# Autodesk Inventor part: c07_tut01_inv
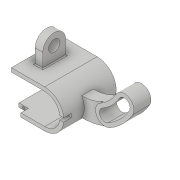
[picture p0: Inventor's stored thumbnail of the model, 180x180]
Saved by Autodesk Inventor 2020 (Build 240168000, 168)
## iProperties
Created: 2017-04
Part Number: c07_tut01_inv
Material: Generic
Document SubType Name: Modeling
Designer: CADCIM 00
Density: 1 g/cm^3
Appearance: Default
Author: CADCIM 00
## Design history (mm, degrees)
sketch "Sketch1"
  geometry: L1 (0, 16)-(35, 16); L2 (35, 16)-(35, 20); L3 (35, 20)-(0, 20); L4 (0, -20)-(35, -20); L5 (35, -20)-(35, -16); L6 (35, -16)-(0, -16); A1 r 16 centre (0, 0) between (0, 16) and (0, -16); A2 r 20 centre (0, 0) between (0, 20) and (0, -20); 1 further point
  constraints: 12 end point, 4 point on circle, 4 tangent, 3 perpendicular, 2 centre point, 2 point on line, 1 coincident, 1 concentric, 1 horizontal, 1 parallel
  dimensions: "d1" = 20 radius of A2; "d3" = 35 distance from line of point (0, 0) L5; "d37" = 16 radius of A1
extrude "Extrusion1" new body sketch "Sketch1" stored distance "d4" = 55; taper "d5" = 0 deg
sketch "Sketch2"
  geometry: A1 r 45 centre (-17.5, 55) between (-56.409, 32.393) and (-17.32, 10); A2 r 65 centre (-17.5, 55) between (-73.702, 22.345) and (-17.321, -10); A3 r 10 centre (-65.055, 27.369) between (-56.409, 32.393) and (-73.702, 22.345); A4 r 20 centre (0, 0) between (0, 20) and (0, -20) reference; A5 r 20 centre (0, 0) between (-17.32, 10) and (-17.321, -10); 1 further point
  constraints: 10 point on circle, 4 centre point, 2 tangent, 1 coincident
  dimensions: "d6" = 45 radius of A1; "d7" = 65 radius of A2; "d8" = 17.5 horizontal distance of point (0, 0) A1.centre; "d9" = 55 vertical distance of point (0, 0) A1.centre; "d10" = 60 deg dimension on A1.centre A3.centre A2.end
extrude "Extrusion2" join sketch "Sketch2" stored distance "d11" = 12; taper "d12" = 0 deg
sketch "Sketch3"
  geometry: A1 r 55 centre (-17.5, 55) between (-65.055, 27.369) and (-44.868, 7.293); A2 r 65 centre (-17.5, 55) between (-73.702, 22.345) and (-49.845, -1.381); A3 r 45 centre (-17.5, 55) between (-56.409, 32.393) and (-39.892, 15.967); A4 r 10 centre (-65.055, 27.369) between (-56.409, 32.393) and (-73.702, 22.345); A5 r 10 centre (-44.868, 7.293) between (-49.845, -1.381) and (-39.892, 15.967); A6 r 45 centre (-17.5, 55) between (-56.409, 32.393) and (-17.32, 10) reference; A7 r 65 centre (-17.5, 55) between (-73.702, 22.345) and (-17.321, -10) reference; A8 r 10 centre (-65.055, 27.369) between (-56.409, 32.393) and (-73.702, 22.345) reference; 1 further point
  constraints: 10 point on circle, 7 tangent, 5 centre point, 1 concentric
  dimensions: "d13" = 30 deg dimension on A1.centre A1.end A1.start
extrude "Extrusion3" join sketch "Sketch3" stored distance "d14" = 18; taper "d15" = 0 deg
sketch "Sketch4"
  geometry: A1 r 55 centre (17.5, 55) between (44.868, 7.293) and (65.055, 27.369); A2 r 61 centre (17.5, 55) between (47.854, 2.088) and (70.243, 24.354); A3 r 49 centre (17.5, 55) between (41.883, 12.497) and (59.867, 30.383); A4 r 6 centre (44.868, 7.293) between (41.883, 12.497) and (47.854, 2.088); A5 r 6 centre (65.055, 27.369) between (70.243, 24.354) and (59.867, 30.383); A6 r 45 centre (17.5, 55) between (39.892, 15.967) and (56.409, 32.393) reference; A7 r 10 centre (65.055, 27.369) between (73.702, 22.345) and (56.409, 32.393) reference; A8 r 10 centre (44.868, 7.293) between (39.892, 15.967) and (49.845, -1.381) reference; 1 further point
  constraints: 10 point on circle, 5 centre point, 4 tangent, 3 concentric
  dimensions: "d16" = 6 radius of A5
extrude "Extrusion4" cut sketch "Sketch4" extent not by distance; stored distance "d17" = 18; taper "d18" = 0 deg
workplane "Work Plane1"
sketch "Sketch5"
  geometry: L1 (0, 39.5)-(15, 39.5); L2 (15, 15.5)-(0, 15.5); L3 (0, 55)-(0, 0) reference; L4 (0, 39.5)-(0, 15.5); L5 (-40, 0)-(0, 0) reference; C1 r 6 at (15, 27.5); A1 r 12 centre (15, 27.5) between (15, 15.5) and (15, 39.5); 1 further point
  constraints: 6 end point, 2 centre point, 2 point on circle, 2 point on line, 2 tangent, 1 coincident, 1 collinear, 1 horizontal, 1 parallel
  dimensions: "d20" = 12 radius of A1; "d21" = 12 diameter of C1; "d22" = 15 distance from line of L3 A1.centre; "d23" = 27.5 distance from line of L5 A1.centre
extrude "Extrusion5" join sketch "Sketch5" distance "d24" = 8; taper "d25" = 0 deg
fillet "Fillet1" dims "d26" = 1
sketch "Sketch6"
  geometry: L1 (-35, -16)-(-35, -20) reference; L2 (-35, -20)-(0, -20) reference; L3 (-35, -16)-(-25, -16); L4 (-25, -16)-(-25, -20); L5 (-25, -20)-(-35, -20); L6 (-35, -20)-(-35, -16); L7 (15.631, 2)-(21.208, 2); L8 (21.208, 2)-(21.208, -2); L9 (21.208, -2)-(15.631, -2); L10 (15.631, -2)-(15.631, 2); A1 r 20 centre (0, 0) between (0, -20) and (0, 20) reference; 1 further point
  constraints: 16 end point, 4 parallel, 2 horizontal, 1 perpendicular, 1 point on line
  dimensions: "d27" = 10 distance of L1.start L3.end; "d28" = 4 distance of L9.end L7.start; "d29" = 2 distance from line of L7 point (0, 0)
extrude "Extrusion6" cut sketch "Sketch6" distance "d30" = 8; taper "d31" = 0 deg
sketch "Sketch7"
  geometry: L1 (-35, -20)-(-35, -16) reference; L2 (-25, -20)-(-35, -20) reference; C1 r 1.25 at (-30, -18); 1 further point
  constraints: 1 centre point
  dimensions: "d32" = 5 distance from line of L1 C1.centre; "d33" = 2 distance from line of L2 C1.centre; "d34" = 2.5 diameter of C1
extrude "Extrusion7" cut sketch "Sketch7" distance "d35" = 4; taper "d36" = 0 deg
body "Solid1"
other parameters: "d19" = -17.5
